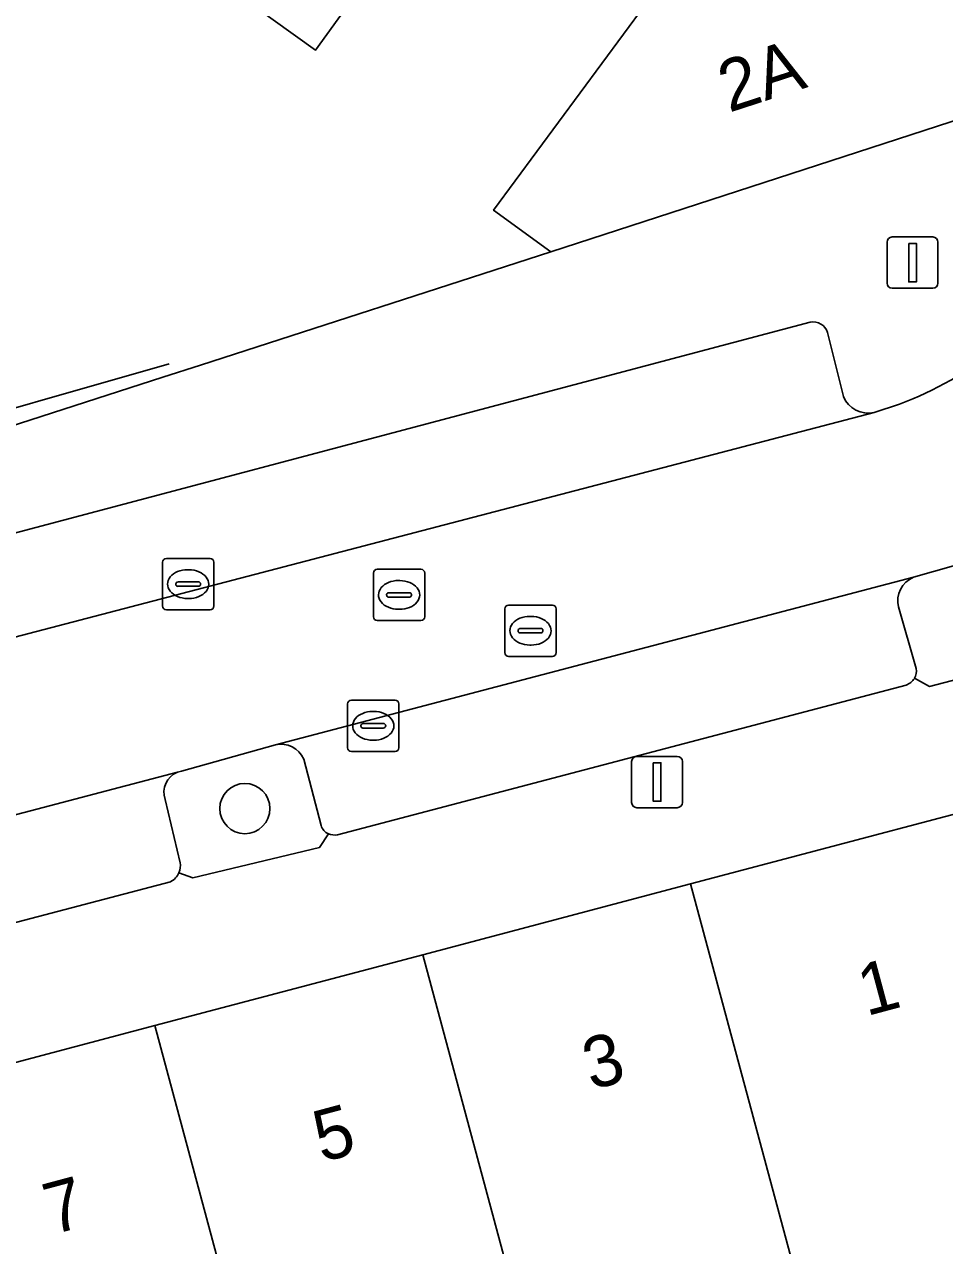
# Model space of a CAD drawing. Extents: x 159716 to 160783, y 383290 to 384031.
# Drawn here: x 160327.37 to 160345.29, y 383671.5 to 383695.29 of the extents above; entities that cross this region are included whole.
import ezdxf

# ---------------------------------------------------------------- set-up
doc = ezdxf.new("R2010")
doc.units = 0
for name, color, linetype in [('IMGEO_Boom', 7, 'Continuous'), ('IMGEO_Erf', 7, 'Continuous'), ('IMGEO_Groenvoorziening', 7, 'Continuous'), ('IMGEO_Kolk', 7, 'Continuous'), ('IMGEO_Lichtmast', 7, 'Continuous'), ('IMGEO_Muur', 7, 'Continuous'), ('IMGEO_Pand', 7, 'Continuous'), ('IMGEO_Pand_nummerreeks', 7, 'Continuous'), ('IMGEO_Parkeervlak_open', 7, 'Continuous'), ('IMGEO_Rijbaan_lokaal_open', 7, 'Continuous'), ('IMGEO_Rioolput', 7, 'Continuous'), ('IMGEO_Voetpad_open', 7, 'Continuous')]:
    doc.layers.add(name, color=color, linetype=linetype)

msp = doc.modelspace()

# ---------------------------------------------------------------- linework, layer by layer
at = {"layer": 'IMGEO_Boom'}
msp.add_circle((160331.66, 383680.011), 0.489, dxfattribs=at)
at = {"layer": 'IMGEO_Erf'}
msp.add_lwpolyline([(160327.047, 383687.439), (160330.061, 383688.414), (160330.794, 383688.651), (160337.621, 383690.859), (160336.505, 383691.665), (160340.303, 383696.817), (160338.508, 383698.102), (160336.481, 383699.555), (160333.034, 383694.781), (160330.562, 383696.566), (160327.807, 383698.555), (160331.167, 383703.206), (160329.688, 383704.274), (160328.279, 383705.291), (160324.92, 383700.64)], dxfattribs=at)
at = {"layer": 'IMGEO_Groenvoorziening'}
for points in [[(160344.7, 383682.548), (160344.996, 383682.391), (160356.794, 383685.473), (160361.049, 383690.367)], [(160345.898, 383684.862), (160344.682, 383684.516)], [(160344.391, 383683.938), (160344.738, 383682.737)], [(160332.255, 383681.251), (160330.424, 383680.74), (160330.346, 383680.717)], [(160333.144, 383679.678), (160332.806, 383680.972)], [(160330.106, 383680.19), (160330.402, 383678.957)], [(160330.376, 383678.761), (160330.644, 383678.664), (160333.115, 383679.254), (160333.288, 383679.52)]]:
    msp.add_lwpolyline(points, dxfattribs=at)
for centre, radius, start, end in [((160344.877, 383684.056), 0.5, 112.9368, 193.6163), ((160344.449, 383682.697), 0.292, 329.3477, 7.9159), ((160332.369, 383680.792), 0.473, 22.3832, 103.9059), ((160330.5, 383680.329), 0.418, 111.6377, 199.3925), ((160333.4, 383679.767), 0.271, 199.1573, 245.5343), ((160330.053, 383678.904), 0.353, 336.1621, 8.7252)]:
    msp.add_arc(centre, radius, start, end, dxfattribs=at)
at = {"layer": 'IMGEO_Kolk'}
for p, q in [((160330.056, 383683.957), (160330.056, 383684.809)), ((160330.131, 383684.883), (160330.983, 383684.883)), ((160331.057, 383684.809), (160331.057, 383683.957)), ((160330.544, 383684.663), (160330.569, 383684.663)), ((160330.315, 383684.377), (160330.315, 383684.389)), ((160330.753, 383684.34), (160330.355, 383684.34)), ((160330.358, 383684.426), (160330.756, 383684.426)), ((160330.799, 383684.389), (160330.799, 383684.377)), ((160330.567, 383684.103), (160330.542, 383684.103)), ((160330.983, 383683.883), (160330.131, 383683.883)), ((160333.735, 383682.123), (160334.587, 383682.123)), ((160333.66, 383681.197), (160333.66, 383682.049)), ((160334.148, 383681.903), (160334.173, 383681.903)), ((160334.661, 383682.049), (160334.661, 383681.197)), ((160333.919, 383681.617), (160333.919, 383681.629)), ((160333.962, 383681.666), (160334.36, 383681.666)), ((160334.403, 383681.629), (160334.403, 383681.617)), ((160334.357, 383681.58), (160333.959, 383681.58)), ((160334.171, 383681.343), (160334.146, 383681.343)), ((160334.587, 383681.123), (160333.735, 383681.123))]:
    msp.add_line(p, q, dxfattribs=at)
for points in [[(160330.056, 383683.957), (160330.056, 383684.809)], [(160330.131, 383684.883), (160330.983, 383684.883)], [(160331.057, 383684.809), (160331.057, 383683.957)], [(160330.983, 383683.883), (160330.131, 383683.883)], [(160333.735, 383682.123), (160334.587, 383682.123)], [(160333.66, 383681.197), (160333.66, 383682.049)], [(160334.661, 383682.049), (160334.661, 383681.197)], [(160334.587, 383681.123), (160333.735, 383681.123)]]:
    msp.add_lwpolyline(points, dxfattribs=at)
for centre, radius, start, end in [((160330.133, 383684.807), 0.0765, 91.552, 178.448), ((160330.133, 383684.807), 0.0765, 91.552, 178.448), ((160330.981, 383684.807), 0.0765, 1.552, 88.448), ((160330.981, 383684.807), 0.0765, 1.552, 88.448), ((160330.355, 383684.386), 0.0403, 85.8775, 175.7526), ((160330.352, 383684.376), 0.0366, 178.938, 274.7102), ((160330.756, 383684.383), 0.043, 264.8664, 352.4533), ((160330.76, 383684.388), 0.0386, 1.7309, 96.639), ((160330.133, 383683.959), 0.0765, 181.552, 268.448), ((160330.133, 383683.959), 0.0765, 181.552, 268.448), ((160330.981, 383683.959), 0.0765, 271.552, 358.448), ((160330.981, 383683.959), 0.0765, 271.552, 358.448), ((160333.737, 383682.047), 0.0765, 91.552, 178.448), ((160333.737, 383682.047), 0.0765, 91.552, 178.448), ((160334.585, 383682.047), 0.0765, 1.552, 88.448), ((160334.585, 383682.047), 0.0765, 1.552, 88.448), ((160333.959, 383681.626), 0.0403, 85.8775, 175.7526), ((160333.956, 383681.616), 0.0366, 178.938, 274.7102), ((160334.36, 383681.623), 0.043, 264.8664, 352.4533), ((160334.364, 383681.628), 0.0386, 1.7309, 96.639), ((160333.737, 383681.199), 0.0765, 181.552, 268.448), ((160333.737, 383681.199), 0.0765, 181.552, 268.448), ((160334.585, 383681.199), 0.0765, 271.552, 358.448), ((160334.585, 383681.199), 0.0765, 271.552, 358.448)]:
    msp.add_arc(centre, radius, start, end, dxfattribs=at)
for centre, major_axis, ratio, start_param, end_param in [((160330.543, 383684.383), (-0.387, 0.002), 0.722429, 4.712389, 7.853982), ((160330.568, 383684.383), (-0.39, 0.002), 0.717154, 1.570796, 4.712389), ((160334.147, 383681.623), (-0.387, 0.002), 0.722429, 4.712389, 7.853982), ((160334.172, 383681.623), (-0.39, 0.002), 0.717154, 1.570796, 4.712389)]:
    msp.add_ellipse(centre, major_axis=major_axis, ratio=ratio, start_param=start_param, end_param=end_param, dxfattribs=at)
at = {"layer": 'IMGEO_Lichtmast'}
for p, q in [((160344.27, 383691.145), (160345.06, 383691.145)), ((160345.06, 383691.145), (160344.27, 383691.145)), ((160344.17, 383690.245), (160344.17, 383691.045)), ((160344.17, 383691.045), (160344.17, 383690.245)), ((160345.16, 383691.045), (160345.16, 383690.245)), ((160345.16, 383690.245), (160345.16, 383691.045)), ((160345.06, 383690.145), (160344.27, 383690.145)), ((160344.27, 383690.145), (160345.06, 383690.145)), ((160339.193, 383680.128), (160339.193, 383680.928)), ((160339.193, 383680.928), (160339.193, 383680.128)), ((160339.293, 383681.028), (160340.083, 383681.028)), ((160340.083, 383681.028), (160339.293, 383681.028)), ((160340.183, 383680.928), (160340.183, 383680.128)), ((160340.183, 383680.128), (160340.183, 383680.928)), ((160340.083, 383680.028), (160339.293, 383680.028)), ((160339.293, 383680.028), (160340.083, 383680.028))]:
    msp.add_line(p, q, dxfattribs=at)
for points in [[(160344.59, 383691.02), (160344.74, 383691.02), (160344.74, 383690.27), (160344.59, 383690.27), (160344.59, 383691.02)], [(160339.613, 383680.903), (160339.763, 383680.903), (160339.763, 383680.153), (160339.613, 383680.153), (160339.613, 383680.903)]]:
    msp.add_lwpolyline(points, dxfattribs=at)
for centre, start, end in [((160344.27, 383691.045), 90, 180), ((160344.27, 383691.045), 90, 180), ((160345.06, 383691.045), 0, 90), ((160345.06, 383691.045), 360, 90), ((160344.27, 383690.245), 180, 270), ((160344.27, 383690.245), 180, 270), ((160345.06, 383690.245), 270, 0), ((160345.06, 383690.245), 270, 0), ((160339.293, 383680.928), 90, 180), ((160339.293, 383680.928), 90, 180), ((160340.083, 383680.928), 0, 90), ((160340.083, 383680.928), 360, 90), ((160339.293, 383680.128), 180, 270), ((160339.293, 383680.128), 180, 270), ((160340.083, 383680.128), 270, 0), ((160340.083, 383680.128), 270, 0)]:
    msp.add_arc(centre, 0.1, start, end, dxfattribs=at)
at = {"layer": 'IMGEO_Muur'}
msp.add_lwpolyline([(160330.189, 383688.675), (160319.647, 383685.659)], dxfattribs=at)
at = {"layer": 'IMGEO_Pand'}
for points in [[(160343.264, 383704.691), (160338.768, 383707.937), (160330.562, 383696.566), (160333.034, 383694.781), (160336.481, 383699.555), (160338.508, 383698.102)], [(160349.136, 383698.245), (160349.244, 383698.263), (160348.839, 383700.762), (160348.73, 383700.744), (160343.264, 383704.691), (160338.508, 383698.102), (160340.303, 383696.817), (160336.505, 383691.665), (160337.621, 383690.859), (160345.67, 383693.475)], [(160346.992, 383675.05), (160345.649, 383679.947), (160340.343, 383678.544), (160344.253, 383663.986), (160347.331, 383664.813), (160345.754, 383670.689), (160348.001, 383671.292)], [(160340.343, 383678.544), (160335.126, 383677.165), (160337.416, 383668.636), (160337.445, 383668.529), (160339.174, 383668.993), (160340.77, 383663.051), (160344.253, 383663.986)], [(160335.126, 383677.165), (160329.908, 383675.785), (160333.816, 383661.236), (160336.918, 383662.069), (160335.336, 383667.962), (160337.445, 383668.529), (160337.416, 383668.636)], [(160329.908, 383675.785), (160324.693, 383674.405), (160326.969, 383665.926), (160327.021, 383665.734), (160328.843, 383666.223), (160330.426, 383660.326), (160333.816, 383661.236)]]:
    msp.add_lwpolyline(points, close=True, dxfattribs=at)
at = {"layer": 'IMGEO_Parkeervlak_open'}
for points in [[(160342.669, 383689.488), (160321.168, 383683.787), (160311.679, 383681.281), (160243.738, 383668.782)], [(160343.318, 383688.039), (160343.01, 383689.282)], [(160243.406, 383666.677), (160265.139, 383670.682), (160268.529, 383671.299), (160312.074, 383679.307), (160320.087, 383681.393), (160323.47, 383682.384), (160343.917, 383687.725)], [(160344.682, 383684.516), (160332.255, 383681.251)], [(160344.738, 383682.737), (160344.391, 383683.938)], [(160333.466, 383679.502), (160344.539, 383682.418)], [(160332.806, 383680.972), (160333.144, 383679.678)], [(160330.346, 383680.717), (160324.345, 383679.14), (160320.96, 383678.239), (160313.442, 383676.239), (160313.418, 383676.249), (160312.57, 383676.075)], [(160330.402, 383678.957), (160330.106, 383680.19)], [(160313.812, 383674.281), (160330.213, 383678.586)]]:
    msp.add_lwpolyline(points, dxfattribs=at)
for centre, radius, start, end in [((160342.723, 383689.193), 0.3, 17.319, 100.4082), ((160343.807, 383688.243), 0.53, 202.6498, 282.0226), ((160344.877, 383684.056), 0.5, 112.9368, 193.6163), ((160344.449, 383682.697), 0.292, 329.3477, 7.9159), ((160344.447, 383682.696), 0.293, 288.2201, 329.6184), ((160332.369, 383680.792), 0.473, 22.3832, 103.9059), ((160330.5, 383680.329), 0.418, 111.6377, 199.3925), ((160333.4, 383679.767), 0.271, 199.1573, 245.5343), ((160333.403, 383679.767), 0.272, 245.0312, 283.4201), ((160330.038, 383678.913), 0.371, 298.2185, 335.8481), ((160330.053, 383678.904), 0.353, 336.1621, 8.7252)]:
    msp.add_arc(centre, radius, start, end, dxfattribs=at)
at = {"layer": 'IMGEO_Rijbaan_lokaal_open'}
msp.add_lwpolyline([(160344.413, 383687.886), (160343.917, 383687.725), (160323.47, 383682.384), (160324.345, 383679.14), (160330.346, 383680.717), (160330.424, 383680.74), (160332.255, 383681.251), (160344.682, 383684.516), (160345.898, 383684.862)], dxfattribs=at)
msp.add_arc((160341.112, 383696.239), 8.981, 291.5623, 319.6019, dxfattribs=at)
at = {"layer": 'IMGEO_Rioolput'}
for p, q in [((160334.163, 383683.747), (160334.163, 383684.599)), ((160334.238, 383684.673), (160335.09, 383684.673)), ((160335.164, 383684.599), (160335.164, 383683.747)), ((160334.651, 383684.453), (160334.676, 383684.453)), ((160334.422, 383684.167), (160334.422, 383684.179)), ((160334.86, 383684.13), (160334.462, 383684.13)), ((160334.465, 383684.216), (160334.863, 383684.216)), ((160334.906, 383684.179), (160334.906, 383684.167)), ((160334.674, 383683.893), (160334.649, 383683.893)), ((160336.723, 383683.049), (160336.723, 383683.901)), ((160336.798, 383683.975), (160337.65, 383683.975)), ((160337.211, 383683.755), (160337.236, 383683.755)), ((160337.724, 383683.901), (160337.724, 383683.049)), ((160335.09, 383683.673), (160334.238, 383683.673)), ((160337.025, 383683.518), (160337.423, 383683.518)), ((160336.982, 383683.469), (160336.982, 383683.481)), ((160337.42, 383683.432), (160337.022, 383683.432)), ((160337.466, 383683.481), (160337.466, 383683.469)), ((160337.234, 383683.195), (160337.209, 383683.195)), ((160337.65, 383682.975), (160336.798, 383682.975))]:
    msp.add_line(p, q, dxfattribs=at)
for points in [[(160334.163, 383683.747), (160334.163, 383684.599)], [(160334.238, 383684.673), (160335.09, 383684.673)], [(160335.164, 383684.599), (160335.164, 383683.747)], [(160336.723, 383683.049), (160336.723, 383683.901)], [(160336.798, 383683.975), (160337.65, 383683.975)], [(160337.724, 383683.901), (160337.724, 383683.049)], [(160335.09, 383683.673), (160334.238, 383683.673)], [(160337.65, 383682.975), (160336.798, 383682.975)]]:
    msp.add_lwpolyline(points, dxfattribs=at)
for centre, radius, start, end in [((160334.24, 383684.597), 0.0765, 91.552, 178.448), ((160334.24, 383684.597), 0.0765, 91.552, 178.448), ((160335.088, 383684.597), 0.0765, 1.552, 88.448), ((160335.088, 383684.597), 0.0765, 1.552, 88.448), ((160334.462, 383684.176), 0.0403, 85.8775, 175.7526), ((160334.459, 383684.166), 0.0366, 178.938, 274.7102), ((160334.863, 383684.173), 0.043, 264.8664, 352.4533), ((160334.867, 383684.178), 0.0386, 1.7309, 96.639), ((160334.24, 383683.749), 0.0765, 181.552, 268.448), ((160334.24, 383683.749), 0.0765, 181.552, 268.448), ((160335.088, 383683.749), 0.0765, 271.552, 358.448), ((160335.088, 383683.749), 0.0765, 271.552, 358.448), ((160336.8, 383683.899), 0.0765, 91.552, 178.448), ((160336.8, 383683.899), 0.0765, 91.552, 178.448), ((160337.648, 383683.899), 0.0765, 1.552, 88.448), ((160337.648, 383683.899), 0.0765, 1.552, 88.448), ((160337.022, 383683.478), 0.0403, 85.8775, 175.7526), ((160337.427, 383683.48), 0.0386, 1.7309, 96.639), ((160337.019, 383683.468), 0.0366, 178.938, 274.7102), ((160337.423, 383683.475), 0.043, 264.8664, 352.4533), ((160336.8, 383683.051), 0.0765, 181.552, 268.448), ((160336.8, 383683.051), 0.0765, 181.552, 268.448), ((160337.648, 383683.051), 0.0765, 271.552, 358.448), ((160337.648, 383683.051), 0.0765, 271.552, 358.448)]:
    msp.add_arc(centre, radius, start, end, dxfattribs=at)
for centre, major_axis, ratio, start_param, end_param in [((160334.65, 383684.173), (-0.387, 0.002), 0.722429, 4.712389, 7.853982), ((160334.675, 383684.173), (-0.39, 0.002), 0.717154, 1.570796, 4.712389), ((160337.21, 383683.475), (-0.387, 0.002), 0.722429, 4.712389, 7.853982), ((160337.235, 383683.475), (-0.39, 0.002), 0.717154, 1.570796, 4.712389)]:
    msp.add_ellipse(centre, major_axis=major_axis, ratio=ratio, start_param=start_param, end_param=end_param, dxfattribs=at)
at = {"layer": 'IMGEO_Voetpad_open'}
for points in [[(160353.13, 383697.593), (160348.839, 383700.762), (160349.244, 383698.263), (160349.136, 383698.245), (160345.67, 383693.475), (160337.621, 383690.859), (160330.794, 383688.651), (160330.061, 383688.414), (160327.047, 383687.439), (160319.035, 383685.301), (160314.651, 383684.131), (160313.952, 383683.934), (160312.906, 383683.638), (160312.924, 383683.546), (160312.056, 383683.385), (160306.633, 383682.393), (160301.328, 383681.422), (160296.023, 383680.451), (160290.718, 383679.478), (160285.413, 383678.507)], [(160319.475, 383673.025), (160324.693, 383674.405), (160329.908, 383675.785), (160335.126, 383677.165), (160340.343, 383678.544), (160345.649, 383679.947), (160347.317, 383680.387), (160358.229, 383683.234), (160363.163, 383688.996), (160361.049, 383690.367), (160356.794, 383685.473), (160344.996, 383682.391), (160344.7, 383682.548)], [(160243.738, 383668.782), (160311.679, 383681.281), (160321.168, 383683.787), (160342.669, 383689.488)], [(160343.01, 383689.282), (160343.318, 383688.039)], [(160343.917, 383687.725), (160344.413, 383687.886)], [(160344.539, 383682.418), (160333.466, 383679.502)], [(160333.288, 383679.52), (160333.115, 383679.254), (160330.644, 383678.664), (160330.376, 383678.761)], [(160330.213, 383678.586), (160313.812, 383674.281)]]:
    msp.add_lwpolyline(points, dxfattribs=at)
for centre, radius, start, end in [((160341.112, 383696.239), 8.981, 291.5623, 319.6019), ((160342.723, 383689.193), 0.3, 17.319, 100.4082), ((160343.807, 383688.243), 0.53, 202.6498, 282.0226), ((160344.447, 383682.696), 0.293, 288.2201, 329.6184), ((160333.403, 383679.767), 0.272, 245.0312, 283.4201), ((160330.038, 383678.913), 0.371, 298.2185, 335.8481)]:
    msp.add_arc(centre, radius, start, end, dxfattribs=at)

# ---------------------------------------------------------------- texts
at = {"layer": 'IMGEO_Pand_nummerreeks'}
for s, rotation, p in [('2A', 18.0023, (160341.088, 383693.563)), ('1', 15.0344, (160343.765, 383675.964)), ('3', 15.0344, (160338.405, 383674.524)), ('5', 15.0344, (160333.156, 383673.115)), ('7', 15.0344, (160327.906, 383671.705))]:
    msp.add_text(s, height=1, rotation=rotation, dxfattribs=at).set_placement(p)

doc.saveas('drawing.dxf')
